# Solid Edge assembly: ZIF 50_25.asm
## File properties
Title: Zylinder
Author: bmolnar
Template: iso metric assembly.asm
Last saved by: psaghy
Revision: 18
Application: Solid Edge
Username: bmolnar
Dokumentum tartalom típus: 1
Document Number: ZIF 50/25
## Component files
Mutter.par
Kolbenstange.par
Profilrohr.par
Kit_2.par
Kit_1.par
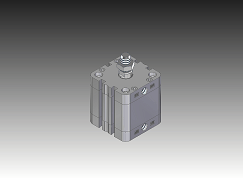
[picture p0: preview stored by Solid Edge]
